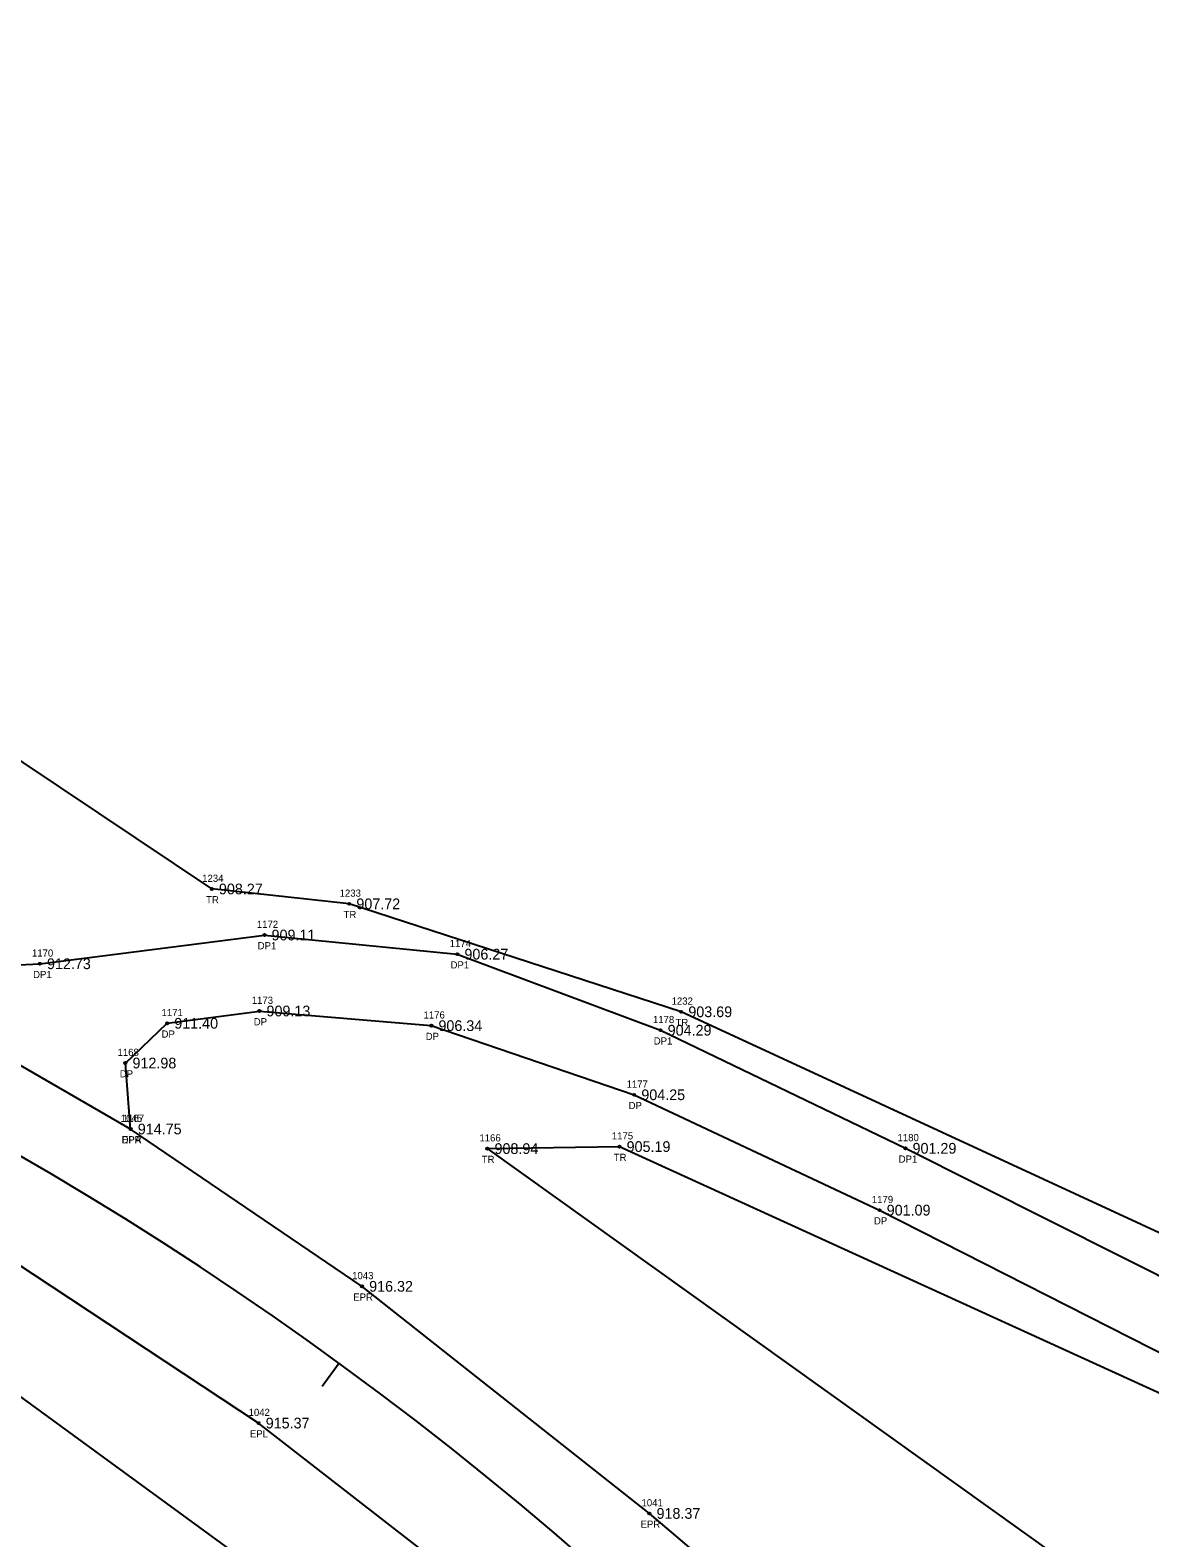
# Model space of a CAD drawing. Extents: x 1393163 to 1398407, y 1072670 to 1074651.
# Drawn here: x 1396812.6 to 1396969.4, y 1074266.9 to 1074477.8 of the extents above; entities that cross this region are included whole.
import ezdxf

# ---------------------------------------------------------------- set-up
doc = ezdxf.new("R2010")
doc.units = 0
for name, color, linetype in [('RD_EX_Driveway', 7, 'Continuous'), ('RD_EX_Driveway_txCode', 7, 'Continuous'), ('RD_EX_Road', 7, 'Continuous'), ('RD_EX_Road_txCode', 7, 'Continuous'), ('RD_EX_TX_Driveway_ELEV', 7, 'Continuous'), ('RD_EX_TX_Road_ELEV', 7, 'Continuous'), ('RD_EX_TX_VEG_ELEV', 7, 'Continuous'), ('RD_EX_VEG', 7, 'Continuous'), ('RD_EX_VEG_txCode', 7, 'Continuous'), ('RD_HC_Cl', 7, 'Continuous'), ('RD_HC_Data_Tic', 7, 'Continuous'), ('RD_SMD_Locator', 7, 'Continuous')]:
    doc.layers.add(name, color=color, linetype=linetype)

msp = doc.modelspace()

# ---------------------------------------------------------------- linework, layer by layer
at = {"layer": 'RD_EX_Driveway'}
for points in [[(1396788.75, 1074345.97), (1396814, 1074347.19), (1396845.44, 1074351.21), (1396872.44, 1074348.53), (1396900.89, 1074337.89), (1396935.17, 1074321.37), (1396975.52, 1074301.17), (1397009.08, 1074288.99), (1397048.05, 1074289.01)], [(1396826.71, 1074324.07), (1396825.97, 1074333.3), (1396831.82, 1074338.86), (1396844.73, 1074340.58), (1396868.8, 1074338.53), (1396897.2, 1074328.86), (1396931.55, 1074312.72), (1396975.46, 1074290.41), (1397006.47, 1074279.3), (1397046.34, 1074278.48)]]:
    msp.add_lwpolyline(points, dxfattribs=at)
at = {"layer": 'RD_EX_Road'}
for points in [[(1397127.02, 1074075.08), (1397087.96, 1074107.09), (1397050.33, 1074139.1), (1397012.08, 1074172.65), (1396975.18, 1074205.06), (1396938.56, 1074237.05), (1396899.33, 1074270.29), (1396859.1, 1074302.06), (1396826.71, 1074324.07), (1396788.75, 1074345.97), (1396771.6, 1074353.88), (1396724.53, 1074372.71), (1396674.59, 1074386.64), (1396624.89, 1074395.26)], [(1397113.03, 1074055.78), (1397073.45, 1074088.2), (1397033.12, 1074122.53), (1397005.07, 1074146.99), (1396959.64, 1074187.05), (1396921.5, 1074220.1), (1396884.1, 1074252.26), (1396844.62, 1074282.93), (1396805.23, 1074308.91), (1396761.89, 1074332.05), (1396716.72, 1074350.46), (1396669.99, 1074363.58), (1396621.68, 1074371.65)]]:
    msp.add_lwpolyline(points, dxfattribs=at)
at = {"layer": 'RD_EX_VEG'}
for points in [[(1397009.65, 1074291.54), (1396903.78, 1074340.47), (1396857.31, 1074355.57), (1396838.07, 1074357.65), (1396801.02, 1074382.43), (1396783.06, 1074391.67), (1396723.05, 1074425.5), (1396738.49, 1074477.8)], [(1396894.17, 1074168.98), (1396933.03, 1074155.57), (1396955.02, 1074151.42), (1396964.49, 1074163.23), (1396875.81, 1074239.54), (1396798.14, 1074296.2), (1396756.06, 1074318.4), (1396711.3, 1074338.97), (1396669.03, 1074354.22), (1396616.02, 1074355.85)], [(1397153.93, 1074137.81), (1397083.5, 1074191.3), (1396998.48, 1074234.23), (1396876.65, 1074321.33), (1396895.14, 1074321.61), (1397002.52, 1074272.66), (1397029.25, 1074267.76)]]:
    msp.add_lwpolyline(points, dxfattribs=at)
at = {"layer": 'RD_HC_Cl'}
msp.add_arc((1396561.57, 1073887.11), 500, 48.8271, 94.0437, dxfattribs=at)
at = {"layer": 'RD_HC_Data_Tic'}
msp.add_line((1396855.9, 1074291.3), (1396853.54, 1074288.07), dxfattribs=at)
at = {"layer": 'RD_SMD_Locator'}
for centre in [(1396838.07, 1074357.65), (1396857.31, 1074355.57), (1396845.44, 1074351.21), (1396872.44, 1074348.53), (1396814, 1074347.19), (1396844.73, 1074340.58), (1396903.78, 1074340.47), (1396831.82, 1074338.86), (1396868.8, 1074338.53), (1396900.89, 1074337.89), (1396825.97, 1074333.3), (1396897.2, 1074328.86), (1396826.71, 1074324.07), (1396826.71, 1074324.07), (1396876.65, 1074321.33), (1396895.14, 1074321.61), (1396935.17, 1074321.37), (1396931.55, 1074312.72), (1396859.1, 1074302.06), (1396844.62, 1074282.93), (1396899.33, 1074270.29)]:
    msp.add_circle(centre, 0.15, dxfattribs=at)

# ---------------------------------------------------------------- texts
at = {"layer": 'RD_EX_Driveway_txCode'}
for s, p in [('1172', (1396844.38, 1074352.21)), ('1174', (1396871.38, 1074349.53)), ('1170', (1396812.9, 1074348.19)), ('DP1', (1396844.5, 1074349.21)), ('DP1', (1396813.06, 1074345.19)), ('DP1', (1396871.5, 1074346.53)), ('1173', (1396843.67, 1074341.58)), ('1171', (1396831.04, 1074339.86)), ('1176', (1396867.72, 1074339.53)), ('1178', (1396899.83, 1074338.89)), ('DP', (1396831.04, 1074336.86)), ('DP', (1396843.95, 1074338.58)), ('DP', (1396868.02, 1074336.53)), ('DP1', (1396899.95, 1074335.89)), ('1168', (1396824.88, 1074334.3)), ('DP', (1396825.19, 1074331.3)), ('1177', (1396896.14, 1074329.86)), ('DP', (1396896.42, 1074326.86)), ('1167', (1396825.63, 1074325.07)), ('DPA', (1396825.45, 1074322.07)), ('1180', (1396934.07, 1074322.37)), ('DP1', (1396934.23, 1074319.37)), ('1179', (1396930.48, 1074313.72)), ('DP', (1396930.77, 1074310.72))]:
    msp.add_text(s, height=1, dxfattribs=at).set_placement(p)
at = {"layer": 'RD_EX_Road_txCode'}
for s, p in [('1045', (1396825.33, 1074325.07)), ('EPR', (1396825.49, 1074322.07)), ('1043', (1396857.72, 1074303.06)), ('EPR', (1396857.88, 1074300.06)), ('1042', (1396843.23, 1074283.93)), ('EPL', (1396843.41, 1074280.93)), ('1041', (1396898.23, 1074271.29)), ('EPR', (1396898.1, 1074268.29))]:
    msp.add_text(s, height=1, dxfattribs=at).set_placement(p)
at = {"layer": 'RD_EX_TX_Driveway_ELEV'}
for s, p in [('909.11', (1396846.44, 1074350.46)), ('906.27', (1396873.44, 1074347.78)), ('912.73', (1396815, 1074346.44)), ('909.13', (1396845.73, 1074339.83)), ('911.40', (1396832.82, 1074338.11)), ('906.34', (1396869.8, 1074337.78)), ('904.29', (1396901.89, 1074337.14)), ('912.98', (1396826.97, 1074332.55)), ('904.25', (1396898.2, 1074328.11)), ('914.75', (1396827.71, 1074323.32)), ('901.29', (1396936.17, 1074320.62)), ('901.09', (1396932.55, 1074311.97))]:
    msp.add_text(s, height=1.5, dxfattribs=at).set_placement(p)
at = {"layer": 'RD_EX_TX_Road_ELEV'}
for s, p in [('914.75', (1396827.71, 1074323.32)), ('916.32', (1396860.1, 1074301.31)), ('915.37', (1396845.62, 1074282.18)), ('918.37', (1396900.33, 1074269.54))]:
    msp.add_text(s, height=1.5, dxfattribs=at).set_placement(p)
at = {"layer": 'RD_EX_TX_VEG_ELEV'}
for s, p in [('908.27', (1396839.07, 1074356.9)), ('907.72', (1396858.31, 1074354.82)), ('903.69', (1396904.78, 1074339.72)), ('908.94', (1396877.65, 1074320.58)), ('905.19', (1396896.14, 1074320.86))]:
    msp.add_text(s, height=1.5, dxfattribs=at).set_placement(p)
at = {"layer": 'RD_EX_VEG_txCode'}
for s, p in [('1234', (1396836.73, 1074358.65)), ('1233', (1396855.97, 1074356.57)), ('TR', (1396837.28, 1074355.65)), ('TR', (1396856.52, 1074353.57)), ('1232', (1396902.44, 1074341.47)), ('TR', (1396902.99, 1074338.47)), ('1166', (1396875.54, 1074322.33)), ('1175', (1396894.08, 1074322.61)), ('TR', (1396875.86, 1074319.33)), ('TR', (1396894.34, 1074319.61))]:
    msp.add_text(s, height=1, dxfattribs=at).set_placement(p)

doc.saveas('drawing.dxf')
